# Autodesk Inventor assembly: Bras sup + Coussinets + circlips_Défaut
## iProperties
Shininess: 64.0
Length Units: 11269
Angle Units: 11279
Time Units: 11290
Mass Units: 11283
Length Display Precision: 3
Angle Display Precision: 2
Compacted: True
Created: 2006-11
Part Number: Bras sup + Coussinets + circlips_Défaut
Document SubType Name: Assembly
Designer: profs_sti
Density: 0.0
Volumn: 0.0
Area: 0.0
PropertySet Name: Model Information
Control State: 0
Master: False
Checked Out: False
Author: profs_sti
